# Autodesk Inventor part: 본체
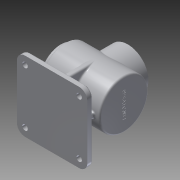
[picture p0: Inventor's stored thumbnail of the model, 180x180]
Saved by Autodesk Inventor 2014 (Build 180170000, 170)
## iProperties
Created: 2015-07
Part Number: 본체
Material: Aluminum 6061
Document SubType Name: Modeling
Designer: user
Density: 2.71 g/cm^3
Appearance: Aluminum - Flat
Mass: 1277.64 g
Surface Area: 1267.64 cm^2
Volume: 471.455 cm^3
Author: user
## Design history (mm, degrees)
node "Sketch1"
sketch "Sketch2"
  geometry: L1 (0, 0)-(110, 0); L2 (0, 0)-(0, 45); L3 (0, 45)-(110, 45); L4 (110, 45)-(110, 0); L5 (7, 0)-(7, 40); L6 (7, 40)-(103, 40); L7 (103, 40)-(103, 0)
  constraints: 14 end point, 4 perpendicular, 2 parallel, 2 point on line, 1 horizontal
  dimensions: "d1" = 110 distance of L1.start L1.end; "d2" = 90 diameter of L3 L1; "d3" = 7 distance between parallel lines of L4 L7; "d4" = 5 distance between parallel lines of L6 L3; "d5" = 96 distance of L5.end L6.end
revolve "Revolution1" sketch "Sketch2" stored, may be unused: angle "d6" = 90 deg
sketch "Sketch3"
  geometry: C1 r 45 at (0, 0) reference; C2 r 38 at (0, 0)
  constraints: 1 centre point, 1 coincident
  dimensions: "d7" = 76 diameter of C2
extrude "Extrusion1" join sketch "Sketch3" distance "d8" = 7; taper "d9" = 0 deg
hole "Hole1" diameter "d12" = 54; stored, may be unused: countersink angle "d16" = 90 deg, drill point angle "d18" = 0 deg; dims "d10" = 10, "d11" = 10, "d13" = 6, "d14" = 4, "d15" = 2, "d17" = 14
workplane "Work Plane1"
sketch "Sketch4"
  geometry: L1 (10, 65)-(-120, 65); L2 (-120, 65)-(-120, -65); L3 (-120, -65)-(10, -65); L4 (10, -65)-(10, 65); L5 (10, 65)-(-120, -65); L6 (-120, 65)-(10, -65); L7 (0, 0)-(-55, 0); 1 further point
  constraints: 14 end point, 2 horizontal, 2 midpoint, 2 parallel, 1 coincident, 1 perpendicular
  dimensions: "d20" = 130 distance of L1.start L1.end; "d21" = 130 distance of L1.end L2.end; "d22" = 55 distance of L7.start L7.end
extrude "Extrusion2" join sketch "Sketch4" distance "d23" = 10; taper "d24" = 0 deg
sketch "Sketch5"
  geometry: L1 (-10, -65)-(120, -65) reference; L2 (120, -65)-(120, 65) reference; L3 (120, 65)-(-10, 65) reference; L4 (-10, 65)-(-10, -65) reference; L5 (-10, -65)-(120, -65) reference; L6 (-10, 65)-(-10, -65) reference; L7 (120, 65)-(-10, 65) reference; L8 (120, -65)-(120, 65) reference; L9 (5, 50)-(105, 50); L10 (105, 50)-(105, -50); L11 (105, -50)-(5, -50); L12 (5, -50)-(5, 50); C1 r 7.5 at (105, 50); C2 r 7.5 at (5, -50); C3 r 7.5 at (105, -50); C4 r 7.5 at (5, 50); 1 further point
  constraints: 8 end point, 4 centre point, 4 coincident, 3 other
  dimensions: "d26" = 5 distance from line of L12 point (0, 0); "d28" = 15 diameter of C1; "d29" = 15 diameter of C2; "d30" = 15 diameter of C3; "d31" = 15 diameter of C4
extrude "Extrusion3" join sketch "Sketch5" distance "d32" = 3; taper "d33" = 0 deg
hole "Hole2" diameter "d36" = 10; stored, may be unused: countersink angle "d40" = 90 deg, drill point angle "d42" = 0 deg; dims "d34" = 10, "d35" = 10, "d37" = 6, "d38" = 4, "d39" = 2, "d41" = 10
hole "Hole3" diameter "d45" = 10; stored, may be unused: countersink angle "d49" = 90 deg, drill point angle "d51" = 0 deg; dims "d43" = 10, "d44" = 10, "d46" = 6, "d47" = 4, "d48" = 2, "d50" = 10
hole "Hole4" diameter "d54" = 10; stored, may be unused: countersink angle "d58" = 90 deg, drill point angle "d60" = 0 deg; dims "d52" = 10, "d53" = 10, "d55" = 6, "d56" = 4, "d57" = 2, "d59" = 10
hole "Hole5" diameter "d63" = 10; stored, may be unused: countersink angle "d67" = 90 deg, drill point angle "d69" = 0 deg; dims "d61" = 10, "d62" = 10, "d64" = 6, "d65" = 4, "d66" = 2, "d68" = 10
sketch "Sketch6"
  geometry: L1 (50, 5)-(60, 5); L2 (60, 5)-(60, -5); L3 (60, -5)-(50, -5); L4 (50, -5)-(50, 5); L5 (50, 5)-(60, -5); L6 (60, 5)-(50, -5); L7 (55, 0)-(0, 0); 1 further point
  constraints: 14 end point, 4 midpoint, 2 horizontal, 2 parallel, 1 perpendicular
  dimensions: "d70" = 10 distance of L2.end L3.end; "d71" = 10 distance of L1.end L2.end; "d72" = 55 distance of L7.start L7.end
extrude "Extrusion4" join sketch "Sketch6" stored distance "d73" = 3; taper "d74" = 0 deg
sketch "Sketch7"
  geometry: L1 (0, -45)-(110, -45) reference; L2 (120, -68)-(-10, -68) reference; L3 (10, -45)-(10, -68); 1 further point
  constraints: 2 end point, 2 point on line, 1 perpendicular
  dimensions: "d75" = 10 distance from line of L3 point (0, 0)
feature "Rib1" sketch "Sketch7" dims "d76" = 1, "d77" = 10, "d78" = 0, "d79" = 0, "d80" = 1, "d81" = 1
workplane "Work Plane2"
mirror "Mirror1"
sketch "Sketch8"
  geometry: L1 (-45, 0)-(-45, -68); L2 (-65, -68)-(65, -68) reference; 1 further point
  constraints: 2 end point, 1 point on line, 1 vertical
  dimensions: "d82" = 68 distance of L1.start L1.end; "d83" = 45 distance from line of point (0, 0) L1
feature "Rib2" sketch "Sketch8" dims "d84" = 1, "d85" = 10, "d86" = 0, "d87" = 0, "d88" = 1, "d89" = 1
mirror "Mirror2"
workplane "Work Plane3"
sketch "Sketch9"
  geometry: L1 (0, 0)-(55, 0); C1 r 38 at (55, 0)
  constraints: 2 end point, 1 centre point, 1 coincident, 1 horizontal
  dimensions: "d91" = 55 distance of L1.start L1.end; "d92" = 76 diameter of C1
extrude "Extrusion5" join sketch "Sketch9" stored distance "d93" = 3; taper "d94" = 0 deg
hole "Hole6" diameter "d97" = 54; stored, may be unused: countersink angle "d101" = 90 deg, drill point angle "d103" = 0 deg; dims "d95" = 10, "d96" = 10, "d98" = 6, "d99" = 4, "d100" = 2, "d102" = 10
sketch "Sketch11"
  geometry: L1 (0, 32)-(0, -32); L2 (-32, 0)-(32, 0); A1 r 32 centre (0, 0) between (0, 32) and (32, 0); 2 further points
  constraints: 6 midpoint, 4 end point, 4 point on circle, 1 centre point, 1 perpendicular, 1 vertical
  dimensions: "d114" = 64 diameter of A1
hole "Hole8" sketch "Sketch11" at (32, 0), (0, 32), (0, -32), (-32, 0) diameter "d115" = 3.242; stored, may be unused: countersink angle "d119" = 90 deg, drill point angle "d121" = 118 deg; dims "d116" = 8, "d117" = 4, "d118" = 2, "d120" = 10
sketch "Sketch12"
  geometry: C1 r 45 at (0, 0) reference; 1 further point
  constraints: 1 coincident, 1 other
emboss "Emboss1" sketch "Sketch12" dims "d122" = 0.5, "d123" = 0
fillet "Fillet1" dims "d124" = 15
fillet "Fillet2" dims "d125" = 3
fillet "Fillet3" dims "d126" = 3
fillet "Fillet4" dims "d127" = 3
fillet "Fillet5" dims "d128" = 3
chamfer "Chamfer1" distance "d129" = 1; stored, may be unused: second distance "d130" = 2, angle "d131" = 45 deg
fillet "Fillet6" dims "d132" = 3
fillet "Fillet7" dims "d133" = 3
chamfer "Chamfer2" distance "d134" = 1; stored, may be unused: second distance "d135" = 2, angle "d136" = 45 deg
sketch "Sketch13"
  geometry: L1 (0, 32)-(0, -32); C1 r 38 at (0, 0) reference; A1 r 32 centre (0, 0) between (0, 32) and (0, -32); 1 further point
  constraints: 2 end point, 2 point on circle, 1 centre point, 1 coincident, 1 midpoint, 1 vertical
  dimensions: "d137" = 64 diameter of A1
hole "Hole9" sketch "Sketch13" at (0, 32) diameter "d138" = 3.242; stored, may be unused: countersink angle "d142" = 90 deg, drill point angle "d144" = 118 deg; dims "d139" = 8, "d140" = 4, "d141" = 2, "d143" = 10
pattern_circular "Circular Pattern1" dims angle "d146" = 360 deg
body "Solid1"
node "Projected Loop1"
other parameters: "d19" = -78
